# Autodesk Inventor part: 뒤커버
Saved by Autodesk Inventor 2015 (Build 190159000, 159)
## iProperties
Created: 2025-08
Part Number: 뒤커버
Material: 일반
Document SubType Name: Modeling
Designer: user
Density: 1 g/cm^3
Appearance: 기본값
Author: user
Author: jhkim
Creation Date: 2025-08-05
Sending System: Autodesk Inventor 2026
Preprocessor: ST-DEVELOPER v20.1
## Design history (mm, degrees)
node "뒤커버1"
node "솔리드1"
node "기준1"
